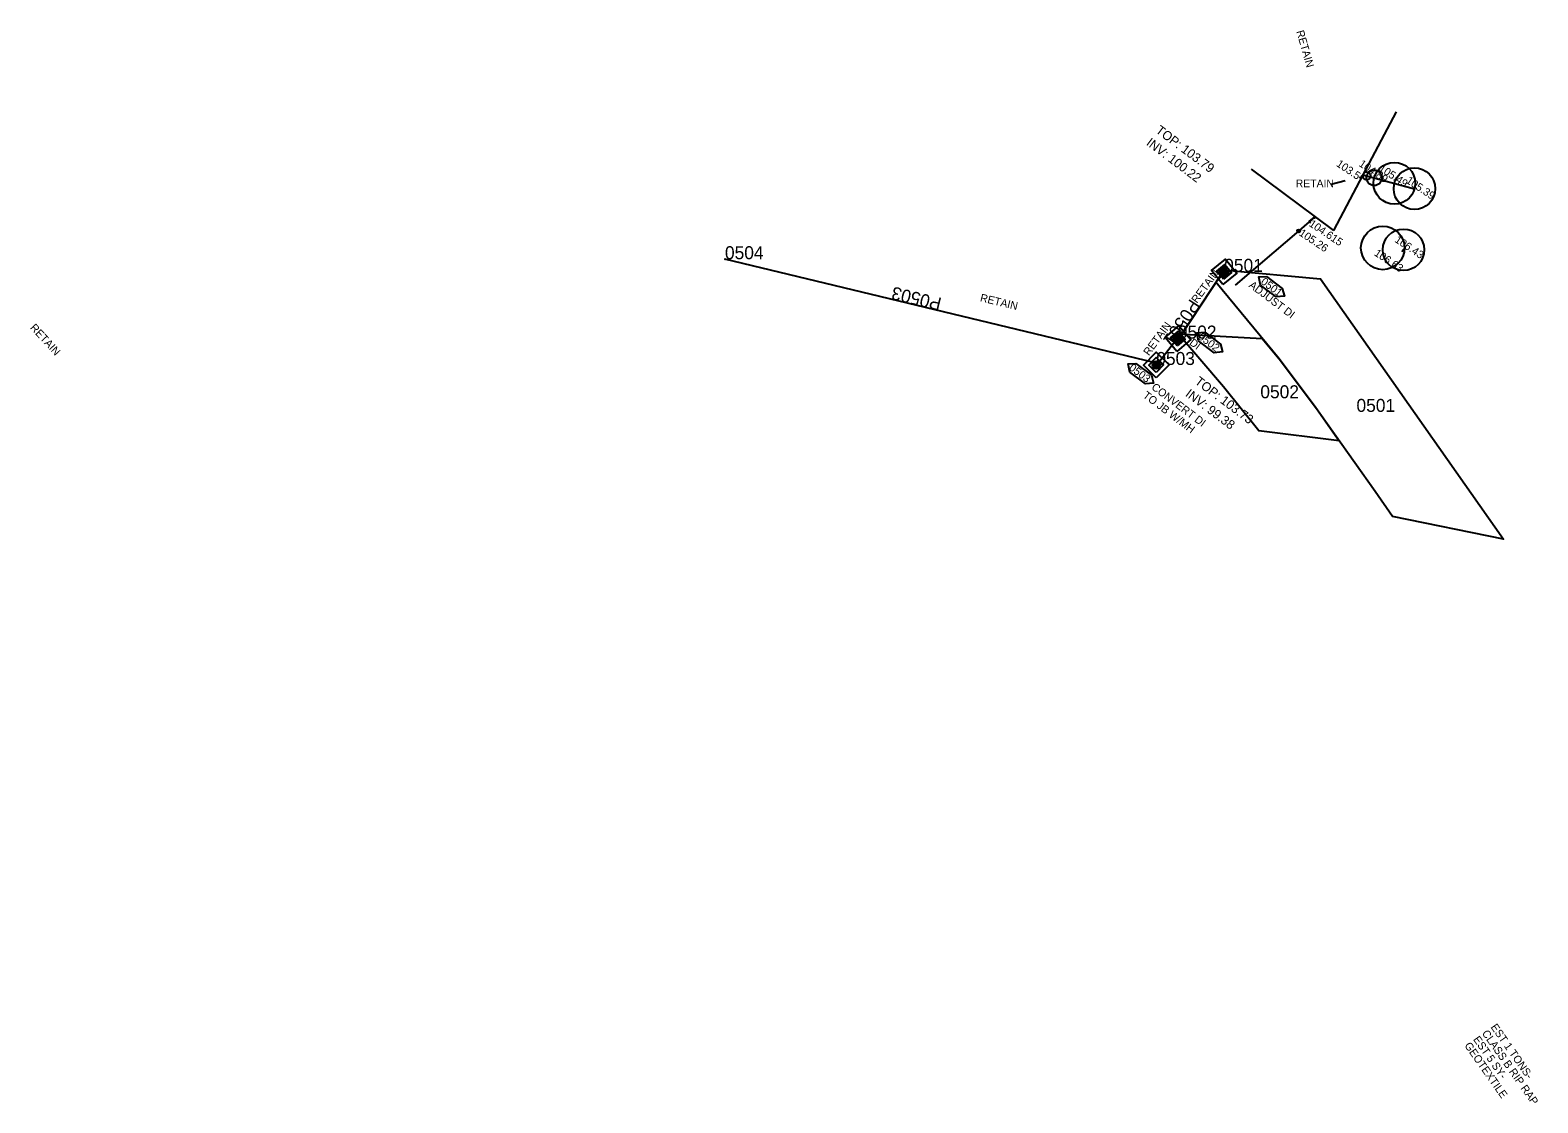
# Model space of a CAD drawing. Extents: x 2296558 to 2299313, y 599200 to 601383.
# Drawn here: x 2297309 to 2297889, y 600349 to 600761 of the extents above; entities that cross this region are included whole.
import ezdxf

# ---------------------------------------------------------------- set-up
doc = ezdxf.new("R2010")
doc.units = 0
for name, color, linetype in [('Default', 7, 'Continuous'), ('Prop Drainage Structure Box Number Symbol CELL', 7, 'Continuous'), ('Prop Drainage Structure Catch Basin Grate 840 03G Label', 7, 'Continuous'), ('Prop Drainage Structure Drop Inlet Adjust CELL', 7, 'Continuous'), ('Prop Drainage Structure Drop Inlet Adjust Label', 7, 'Continuous'), ('Prop Drainage Structure Drop Inlet Grate 840 16 CELL', 7, 'Continuous'), ('Prop Drainage Structure Drop Inlet Grate 840 16 Label', 7, 'Continuous'), ('Prop Drainage Structure Junction Box with Manhole Convert From Drop Inlet CELL', 7, 'Continuous'), ('Prop Drainage Structure Junction Box with Manhole Convert From Drop Inlet Label', 7, 'Continuous'), ('Prop Drainage Structure Outlet Generic CELL', 7, 'Continuous'), ('Prop Drainage Structure Plot Symbol 20 Scale', 7, 'Continuous'), ('Prop Drainage Structure Plot Symbol 50 Scale', 7, 'Continuous'), ('Prop Drainage Structure Retain Label', 7, 'Continuous'), ('Prop Drainage Structure Tops and Inverts LABEL', 7, 'Continuous'), ('Prop Erosion Rip Rap Class B Label', 7, 'Continuous'), ('Prop Plan Preparation Watershed Post Construction', 7, 'Continuous'), ('Scratch_Level_1', 7, 'Continuous'), ('Scratch_Level_3', 7, 'Continuous'), ('Scratch_Level_5', 7, 'Continuous'), ('Scratch_Level_9', 7, 'Continuous')]:
    doc.layers.add(name, color=color, linetype=linetype)

msp = doc.modelspace()

# ---------------------------------------------------------------- linework, layer by layer
at = {"layer": 'Default'}
msp.add_arc((2297742.05, 600632.5), 0.0834, 225.11792, 225.11792, dxfattribs=at)
at = {"layer": 'Prop Drainage Structure Box Number Symbol CELL'}
for points in [[(2297784.49, 600666.54), (2297790.53, 600661.99), (2297791.33, 600658.96), (2297788.15, 600658.67), (2297782.11, 600663.22), (2297781.48, 600666.38), (2297784.49, 600666.54)], [(2297760.72, 600645.09), (2297766.76, 600640.54), (2297767.56, 600637.51), (2297764.38, 600637.22), (2297758.34, 600641.77), (2297757.72, 600644.93), (2297760.72, 600645.09)], [(2297734.21, 600633.11), (2297740.25, 600628.56), (2297741.05, 600625.53), (2297737.87, 600625.24), (2297731.83, 600629.79), (2297731.2, 600632.95), (2297734.21, 600633.11)]]:
    msp.add_lwpolyline(points, dxfattribs=at)
at = {"layer": 'Prop Drainage Structure Catch Basin Grate 840 03G Label'}
msp.add_line((2297809.38, 600702.04), (2297814.73, 600703.48), dxfattribs=at)
at = {"layer": 'Prop Drainage Structure Drop Inlet Adjust CELL'}
for p, q in [((2297767.08, 600669.7), (2297767.08, 600669.7)), ((2297767.21, 600667.55), (2297767.21, 600667.55)), ((2297767.28, 600667.61), (2297769.08, 600669.06)), ((2297768.18, 600668.34), (2297768.18, 600668.34)), ((2297769.15, 600669.12), (2297769.15, 600669.12)), ((2297769.28, 600666.97), (2297769.28, 600666.97))]:
    msp.add_line(p, q, dxfattribs=at)
for points in [[(2297768.31, 600666.19), (2297766.11, 600668.91), (2297768.06, 600670.48), (2297770.25, 600667.76), (2297768.31, 600666.19)], [(2297768.32, 600666.31), (2297766.23, 600668.9), (2297768.04, 600670.37), (2297770.14, 600667.77), (2297768.32, 600666.31)], [(2297767.28, 600667.61), (2297769.08, 600669.06), (2297770.12, 600667.77), (2297768.32, 600666.32), (2297766.24, 600668.9), (2297768.04, 600670.35), (2297769.08, 600669.06)], [(2297767.43, 600667.89), (2297767.3, 600667.78), (2297766.42, 600668.87), (2297766.55, 600668.98), (2297767.43, 600667.89)], [(2297767.64, 600668.06), (2297767.51, 600667.95), (2297766.63, 600669.04), (2297766.76, 600669.14), (2297767.64, 600668.06)], [(2297767.84, 600668.22), (2297767.71, 600668.12), (2297766.84, 600669.2), (2297766.97, 600669.31), (2297767.84, 600668.22)], [(2297768.05, 600668.39), (2297767.92, 600668.28), (2297767.04, 600669.37), (2297767.17, 600669.48), (2297768.05, 600668.39)], [(2297768.26, 600668.56), (2297768.13, 600668.45), (2297767.25, 600669.54), (2297767.38, 600669.64), (2297768.26, 600668.56)], [(2297768.46, 600668.72), (2297768.33, 600668.62), (2297767.46, 600669.7), (2297767.59, 600669.81), (2297768.46, 600668.72)], [(2297768.46, 600666.61), (2297768.33, 600666.5), (2297767.46, 600667.59), (2297767.59, 600667.69), (2297768.46, 600666.61)], [(2297767.79, 600669.98), (2297768.67, 600668.89), (2297768.54, 600668.79), (2297767.66, 600669.87), (2297767.79, 600669.98)], [(2297768.67, 600666.78), (2297768.54, 600666.67), (2297767.66, 600667.76), (2297767.79, 600667.86), (2297768.67, 600666.78)], [(2297768.03, 600670.17), (2297768.91, 600669.08), (2297768.75, 600668.95), (2297767.87, 600670.04), (2297768.03, 600670.17)], [(2297768.88, 600666.94), (2297768.75, 600666.84), (2297767.87, 600667.92), (2297768, 600668.03), (2297768.88, 600666.94)], [(2297769.08, 600667.11), (2297768.95, 600667), (2297768.08, 600668.09), (2297768.21, 600668.2), (2297769.08, 600667.11)], [(2297769.29, 600667.28), (2297769.16, 600667.17), (2297768.28, 600668.26), (2297768.41, 600668.36), (2297769.29, 600667.28)], [(2297769.5, 600667.44), (2297769.37, 600667.34), (2297768.49, 600668.42), (2297768.62, 600668.53), (2297769.5, 600667.44)], [(2297768.83, 600668.7), (2297769.7, 600667.61), (2297769.57, 600667.5), (2297768.7, 600668.59), (2297768.83, 600668.7)], [(2297769.06, 600668.89), (2297769.94, 600667.8), (2297769.78, 600667.67), (2297768.9, 600668.76), (2297769.06, 600668.89)]]:
    msp.add_lwpolyline(points, dxfattribs=at)
at = {"layer": 'Prop Drainage Structure Drop Inlet Grate 840 16 CELL'}
for p, q in [((2297749.22, 600643.99), (2297749.22, 600643.99)), ((2297749.4, 600641.85), (2297749.4, 600641.85)), ((2297750.35, 600642.66), (2297750.35, 600642.66)), ((2297751.31, 600643.46), (2297751.31, 600643.46)), ((2297751.49, 600641.32), (2297751.49, 600641.32))]:
    msp.add_line(p, q, dxfattribs=at)
for points in [[(2297750.53, 600640.51), (2297748.27, 600643.18), (2297750.18, 600644.8), (2297752.44, 600642.13), (2297752.44, 600642.13), (2297750.53, 600640.51)], [(2297750.54, 600640.63), (2297748.39, 600643.17), (2297750.17, 600644.68), (2297752.32, 600642.14), (2297752.32, 600642.14), (2297750.54, 600640.63)], [(2297751.24, 600643.4), (2297749.47, 600641.91), (2297748.4, 600643.17), (2297750.17, 600644.67), (2297752.31, 600642.14), (2297750.54, 600640.64), (2297749.47, 600641.91)], [(2297749.49, 600642.08), (2297748.58, 600643.15), (2297748.71, 600643.25), (2297749.61, 600642.19), (2297749.49, 600642.08)], [(2297749.69, 600642.25), (2297748.79, 600643.32), (2297748.91, 600643.43), (2297749.82, 600642.36), (2297749.69, 600642.25)], [(2297749.89, 600642.43), (2297748.99, 600643.49), (2297749.11, 600643.6), (2297750.02, 600642.53), (2297749.89, 600642.43)], [(2297750.09, 600642.6), (2297749.19, 600643.66), (2297749.32, 600643.77), (2297750.22, 600642.71), (2297750.09, 600642.6)], [(2297750.3, 600642.77), (2297749.39, 600643.83), (2297749.52, 600643.94), (2297750.42, 600642.88), (2297750.3, 600642.77)], [(2297750.5, 600642.94), (2297749.6, 600644.01), (2297749.72, 600644.11), (2297750.63, 600643.05), (2297750.5, 600642.94)], [(2297750.55, 600640.83), (2297749.65, 600641.89), (2297749.77, 600642), (2297750.68, 600640.93), (2297750.55, 600640.83)], [(2297750.7, 600643.11), (2297749.8, 600644.18), (2297749.93, 600644.29), (2297750.83, 600643.22), (2297750.7, 600643.11)], [(2297750.75, 600641), (2297749.85, 600642.06), (2297749.98, 600642.17), (2297750.88, 600641.11), (2297750.75, 600641)], [(2297750.9, 600643.28), (2297750, 600644.35), (2297750.16, 600644.48), (2297751.06, 600643.42), (2297750.9, 600643.28), (2297750.9, 600643.28)], [(2297750.96, 600641.17), (2297750.05, 600642.23), (2297750.18, 600642.34), (2297751.08, 600641.28), (2297750.96, 600641.17)], [(2297751.16, 600641.34), (2297750.25, 600642.41), (2297750.38, 600642.51), (2297751.29, 600641.45), (2297751.16, 600641.34)], [(2297751.36, 600641.51), (2297750.46, 600642.58), (2297750.58, 600642.69), (2297751.49, 600641.62), (2297751.36, 600641.51)], [(2297751.56, 600641.69), (2297750.66, 600642.75), (2297750.79, 600642.86), (2297751.69, 600641.79), (2297751.56, 600641.69)], [(2297751.77, 600641.86), (2297750.86, 600642.92), (2297750.99, 600643.03), (2297751.89, 600641.97), (2297751.77, 600641.86)], [(2297751.97, 600642.03), (2297751.07, 600643.09), (2297751.22, 600643.23), (2297752.13, 600642.16), (2297751.97, 600642.03), (2297751.97, 600642.03)]]:
    msp.add_lwpolyline(points, dxfattribs=at)
at = {"layer": 'Prop Drainage Structure Junction Box with Manhole Convert From Drop Inlet CELL'}
for p, q in [((2297741.07, 600633.47), (2297741.07, 600633.47)), ((2297741.07, 600631.52), (2297741.07, 600631.52)), ((2297742.05, 600632.5), (2297742.05, 600632.5)), ((2297743.03, 600633.48), (2297743.03, 600633.48)), ((2297743.03, 600631.52), (2297743.03, 600631.52))]:
    msp.add_line(p, q, dxfattribs=at)
for points in [[(2297740.72, 600632.12), (2297741.1, 600632.22), (2297741.09, 600632.26), (2297740.71, 600632.16)], [(2297741.05, 600633.46), (2297741.33, 600633.18), (2297741.36, 600633.21), (2297741.08, 600633.49)], [(2297741.71, 600631.15), (2297741.82, 600631.54), (2297741.78, 600631.55), (2297741.67, 600631.16)], [(2297742.39, 600633.84), (2297742.28, 600633.46), (2297742.32, 600633.45), (2297742.43, 600633.83)], [(2297743.05, 600631.53), (2297742.77, 600631.81), (2297742.74, 600631.78), (2297743.02, 600631.5)], [(2297743.38, 600632.88), (2297743, 600632.78), (2297743.01, 600632.74), (2297743.39, 600632.84)]]:
    msp.add_lwpolyline(points, dxfattribs=at)
for radius in [1.39, 0.99, 0.953, 0.87, 0.625, 0.583, 0.333, 0.292, 0.0834, 0.0416]:
    msp.add_circle((2297742.05, 600632.5), radius, dxfattribs=at)
at = {"layer": 'Prop Drainage Structure Outlet Generic CELL'}
msp.add_line((2297576.1, 600673.2), (2297576.1, 600673.2), dxfattribs=at)
msp.add_line((2297576.1, 600673.2), (2297576.1, 600673.2), dxfattribs=at)
msp.add_circle((2297576.1, 600673.2), 0.035, dxfattribs=at)
at = {"layer": 'Prop Drainage Structure Plot Symbol 20 Scale'}
for points in [[(2297767.88, 600665.52), (2297765.37, 600668.64), (2297768.48, 600671.15), (2297770.99, 600668.04)], [(2297750.12, 600639.84), (2297747.54, 600642.89), (2297750.59, 600645.47), (2297753.17, 600642.42)], [(2297742.06, 600629.67), (2297739.22, 600632.49), (2297742.04, 600635.33), (2297744.88, 600632.5)]]:
    msp.add_lwpolyline(points, close=True, dxfattribs=at)
msp.add_circle((2297742.05, 600632.5), 1.5, dxfattribs=at)
at = {"layer": 'Prop Drainage Structure Plot Symbol 50 Scale'}
for points in [[(2297767.66, 600663.41), (2297763.26, 600668.86), (2297768.71, 600673.26), (2297773.1, 600667.81)], [(2297749.95, 600637.72), (2297745.42, 600643.06), (2297750.76, 600647.59), (2297755.29, 600642.25)], [(2297742.06, 600627.55), (2297737.1, 600632.49), (2297742.04, 600637.45), (2297747, 600632.51)]]:
    msp.add_lwpolyline(points, close=True, dxfattribs=at)
msp.add_circle((2297742.05, 600632.5), 1.5, dxfattribs=at)
at = {"layer": 'Prop Plan Preparation Watershed Post Construction'}
for points in [[(2297768.94, 600668.99), (2297805.27, 600665.63), (2297875.68, 600565.5), (2297833, 600574.16), (2297826.21, 600583.83), (2297802.83, 600616.94), (2297789.35, 600634.81), (2297765.03, 600664.33)], [(2297750.46, 600644.47), (2297782.85, 600642.7), (2297789.35, 600634.81), (2297803.69, 600615.72), (2297812.48, 600603.28), (2297781.47, 600607.15), (2297767.98, 600624.04)]]:
    msp.add_lwpolyline(points, close=True, dxfattribs=at)
at = {"layer": 'Scratch_Level_1'}
for p, q in [((2297778.5, 600707.88), (2297803.22, 600689.51)), ((2297821.59, 600705.68), (2297841.39, 600700.33)), ((2297837.77, 600677.62), (2297836.56, 600676.01))]:
    msp.add_line(p, q, dxfattribs=at)
for points in [[(2297834.32, 600729.9), (2297821.55, 600705.69), (2297810.26, 600684.28)], [(2297778.5, 600707.88), (2297803.22, 600689.51), (2297810.26, 600684.28)], [(2297820.14, 600704.81), (2297820.55, 600704.5), (2297821.55, 600705.69)], [(2297802.99, 600689.32), (2297796.84, 600684.08), (2297772.4, 600663.27)], [(2297801.49, 600687.17), (2297800.84, 600687.65), (2297802.99, 600689.32)]]:
    msp.add_lwpolyline(points, dxfattribs=at)
for centre, radius in [((2297822.99, 600705.3), 1.5), ((2297825.89, 600704.52), 3), ((2297833.66, 600702.42), 8.04), ((2297841.39, 600700.33), 8), ((2297802.99, 600689.32), 0.3), ((2297796.84, 600684.08), 0.601), ((2297829.2, 600677.54), 8.38), ((2297837.17, 600676.82), 8)]:
    msp.add_circle(centre, radius, dxfattribs=at)
at = {"layer": 'Scratch_Level_9'}
for p, q in [((2297741.07, 600633.47), (2297576.1, 600673.2)), ((2297767.21, 600667.55), (2297751.31, 600643.46)), ((2297749.4, 600641.85), (2297743.03, 600633.48))]:
    msp.add_line(p, q, dxfattribs=at)

# ---------------------------------------------------------------- texts
at = {"layer": 'Prop Drainage Structure Box Number Symbol CELL'}
for s, p in [('0501', (2297782, 600664)), ('0502', (2297757.89, 600642.8)), ('0503', (2297731.29, 600630.88))]:
    msp.add_text(s, height=3, rotation=323.00028, dxfattribs=at).set_placement(p)
at = {"layer": 'Prop Drainage Structure Drop Inlet Adjust Label'}
msp.add_text('ADJUST DI', height=3, rotation=323.00028, dxfattribs=at).set_placement((2297777.41, 600662.69))
at = {"layer": 'Prop Drainage Structure Drop Inlet Grate 840 16 Label'}
msp.add_text('DI', height=3, rotation=323.00028, dxfattribs=at).set_placement((2297754.52, 600640.57))
at = {"layer": 'Prop Drainage Structure Junction Box with Manhole Convert From Drop Inlet Label'}
for s, p in [('CONVERT DI', (2297739.92, 600623.42)), ('TO JB W/MH', (2297736.65, 600620.26))]:
    msp.add_text(s, height=3, rotation=323.00028, dxfattribs=at).set_placement(p)
at = {"layer": 'Prop Drainage Structure Outlet Generic CELL'}
msp.add_text('O', height=0.05, dxfattribs=at).set_placement((2297576.09, 600673.17))
at = {"layer": 'Prop Drainage Structure Retain Label'}
for rotation, p in [(286.04996, (2297795.89, 600760.81)), (53.71889, (2297757.71, 600656.02)), (346.55083, (2297674.08, 600657.05)), (312.56, (2297308.57, 600646.68)), (53.71889, (2297739.24, 600635.83))]:
    msp.add_text('RETAIN', height=3, rotation=rotation, dxfattribs=at).set_placement(p)
msp.add_text('RETAIN', height=3, dxfattribs=at).set_placement((2297795.71, 600700.86))
at = {"layer": 'Prop Drainage Structure Tops and Inverts LABEL'}
for s, p in [('TOP: 103.79', (2297741.54, 600722.17)), ('INV: 100.22', (2297737.93, 600717.38)), ('TOP: 103.73', (2297756.59, 600625.56)), ('INV: 99.38', (2297752.97, 600620.77))]:
    msp.add_text(s, height=3.5, rotation=323.00028, dxfattribs=at).set_placement(p)
at = {"layer": 'Prop Erosion Rip Rap Class B Label'}
for s, p in [('CLASS B RIP RAP', (2297867.19, 600375.38)), ('EST 1 TONS-', (2297870.56, 600377.75)), ('GEOTEXTILE', (2297860.46, 600370.65)), ('EST 5 SY-', (2297863.83, 600373.02))]:
    msp.add_text(s, height=3, rotation=305.12937, dxfattribs=at).set_placement(p)
at = {"layer": 'Scratch_Level_1'}
for s, p in [('103.5', (2297811.03, 600709.24)), ('104.89', (2297819.73, 600709.22)), ('105.49', (2297827.38, 600707.5)), ('105.39', (2297837.86, 600702.8)), ('105.26', (2297796.71, 600682.6)), ('104.615', (2297800.53, 600686.17)), ('106.63', (2297825.62, 600674.89)), ('106.43', (2297833.52, 600680.04))]:
    msp.add_text(s, height=3, rotation=326.15943, dxfattribs=at).set_placement(p)
for s, p in [('0502', (2297782.08, 600619.7)), ('0501', (2297819.08, 600614.45))]:
    msp.add_text(s, height=5, dxfattribs=at).set_placement(p)
at = {"layer": 'Scratch_Level_3'}
for s, rotation, p in [('P0503', 166.4616, (2297659.76, 600658.2)), ('P0501', 236.56938, (2297755.09, 600658.26))]:
    msp.add_text(s, height=5, rotation=rotation, dxfattribs=at).set_placement(p)
at = {"layer": 'Scratch_Level_5'}
for s, p in [('0504', (2297576.1, 600673.2)), ('0501', (2297768.18, 600668.34)), ('0502', (2297750.35, 600642.66)), ('0503', (2297742.05, 600632.5))]:
    msp.add_text(s, height=5, dxfattribs=at).set_placement(p)

doc.saveas('drawing.dxf')
